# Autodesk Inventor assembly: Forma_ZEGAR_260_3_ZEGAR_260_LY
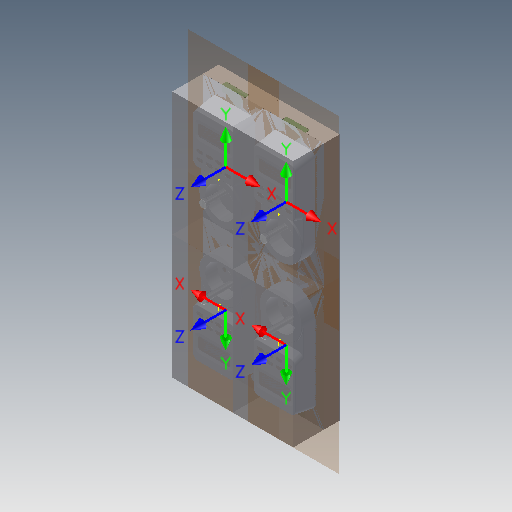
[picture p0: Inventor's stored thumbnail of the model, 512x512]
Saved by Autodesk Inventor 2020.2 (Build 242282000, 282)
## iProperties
Created: 2015-01
Part Number: Forma_ZEGAR_260_3_ZEGAR_260_LY
Document SubType Name: Assembly
Designer: F.Stasiak
Catalog Web Link: www.expertbooks.pl
Manager: www.cadconsulting.pl
Company: Fabian Stasiak CAD Consulting
Author: F.Stasiak
Subject: Zbiór ćwiczeń. Autodesk Inventor 2020. Kurs Professional
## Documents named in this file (10)
- C:\2020_Kurs_Professional\R6 Formy\Komponenty\Forma_ZEGAR_260_3_ZEGAR_260_LY.iam
- C:\2020_Kurs_Professional\R6 Formy\Komponenty\Forma_ZEGAR_260_3_ZEGAR_260_PZ.iam
- C:\2020_Kurs_Professional\R6 Formy\Komponenty\Forma_ZEGAR_260_3_ZEGAR_260_CV_2.ipt
- C:\2020_Kurs_Professional\R6 Formy\Komponenty\Forma_ZEGAR_260_3_ZEGAR_260_CV_3.ipt
- C:\2020_Kurs_Professional\R6 Formy\Komponenty\Forma_ZEGAR_260_3_ZEGAR_260_CV_4.ipt
- C:\2020_Kurs_Professional\R6 Formy\Komponenty\Forma_ZEGAR_260_3_ZEGAR_260_CV_1.ipt
- C:\2020_Kurs_Professional\R6 Formy\Komponenty\Forma_ZEGAR_260_3_ZEGAR_260_CR_2.ipt
- C:\2020_Kurs_Professional\R6 Formy\Komponenty\Forma_ZEGAR_260_3_ZEGAR_260_CR_3.ipt
- C:\2020_Kurs_Professional\R6 Formy\Komponenty\Forma_ZEGAR_260_3_ZEGAR_260_CR_4.ipt
- C:\2020_Kurs_Professional\R6 Formy\Komponenty\Forma_ZEGAR_260_3_ZEGAR_260_CR_1.ipt
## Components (12 placed, 9 different names)
1. Forma_ZEGAR_260_3_ZEGAR_260_PZ:1 [sub-assembly] — Równoległy:1, Równoległy:2, Równoległy:3, Równoległy:13, Równoległy:14, Równoległy:15, Równoległy:25, Równoległy:26, Równoległy:27
2. Forma_ZEGAR_260_3_ZEGAR_260_PZ:2 [sub-assembly] — Równoległy:4, Równoległy:5, Równoległy:6, Równoległy:16, Równoległy:17, Równoległy:18, Równoległy:28, Równoległy:29, Równoległy:30
3. Forma_ZEGAR_260_3_ZEGAR_260_PZ:3 [sub-assembly] — Równoległy:7, Równoległy:8, Równoległy:9, Równoległy:19, Równoległy:20, Równoległy:21, Równoległy:31, Równoległy:32, Równoległy:33
4. Forma_ZEGAR_260_3_ZEGAR_260_PZ:4 [sub-assembly] — Równoległy:10, Równoległy:11, Równoległy:12, Równoległy:22, Równoległy:23, Równoległy:24, Równoległy:34, Równoległy:35, Równoległy:36
5. Forma_ZEGAR_260_3_ZEGAR_260_CV_1:1 — Równoległy:13, Równoległy:14, Równoległy:15
6. Forma_ZEGAR_260_3_ZEGAR_260_CV_2:1 — Równoległy:16, Równoległy:17, Równoległy:18
7. Forma_ZEGAR_260_3_ZEGAR_260_CV_3:1 — Równoległy:19, Równoległy:20, Równoległy:21
8. Forma_ZEGAR_260_3_ZEGAR_260_CV_4:1 — Równoległy:22, Równoległy:23, Równoległy:24
9. Forma_ZEGAR_260_3_ZEGAR_260_CR_1:1 — Równoległy:25, Równoległy:26, Równoległy:27
10. Forma_ZEGAR_260_3_ZEGAR_260_CR_2:1 — Równoległy:28, Równoległy:29, Równoległy:30
11. Forma_ZEGAR_260_3_ZEGAR_260_CR_3:1 — Równoległy:31, Równoległy:32, Równoległy:33
12. Forma_ZEGAR_260_3_ZEGAR_260_CR_4:1 — Równoległy:34, Równoległy:35, Równoległy:36
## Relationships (36: Flush 36)
- Równoległy:1 [Flush]: Forma_ZEGAR_260_3_ZEGAR_260_PZ:1
- Równoległy:2 [Flush]: Forma_ZEGAR_260_3_ZEGAR_260_PZ:1
- Równoległy:3 [Flush]: Forma_ZEGAR_260_3_ZEGAR_260_PZ:1
- Równoległy:4 [Flush]: Forma_ZEGAR_260_3_ZEGAR_260_PZ:2
- Równoległy:5 [Flush]: Forma_ZEGAR_260_3_ZEGAR_260_PZ:2
- Równoległy:6 [Flush]: Forma_ZEGAR_260_3_ZEGAR_260_PZ:2
- Równoległy:7 [Flush]: Forma_ZEGAR_260_3_ZEGAR_260_PZ:3
- Równoległy:8 [Flush]: Forma_ZEGAR_260_3_ZEGAR_260_PZ:3
- Równoległy:9 [Flush]: Forma_ZEGAR_260_3_ZEGAR_260_PZ:3
- Równoległy:10 [Flush]: Forma_ZEGAR_260_3_ZEGAR_260_PZ:4
- Równoległy:11 [Flush]: Forma_ZEGAR_260_3_ZEGAR_260_PZ:4
- Równoległy:12 [Flush]: Forma_ZEGAR_260_3_ZEGAR_260_PZ:4
- Równoległy:13 [Flush]: Forma_ZEGAR_260_3_ZEGAR_260_PZ:1 ↔ Forma_ZEGAR_260_3_ZEGAR_260_CV_1:1
- Równoległy:14 [Flush]: Forma_ZEGAR_260_3_ZEGAR_260_PZ:1 ↔ Forma_ZEGAR_260_3_ZEGAR_260_CV_1:1
- Równoległy:15 [Flush]: Forma_ZEGAR_260_3_ZEGAR_260_PZ:1 ↔ Forma_ZEGAR_260_3_ZEGAR_260_CV_1:1
- Równoległy:16 [Flush]: Forma_ZEGAR_260_3_ZEGAR_260_PZ:2 ↔ Forma_ZEGAR_260_3_ZEGAR_260_CV_2:1
- Równoległy:17 [Flush]: Forma_ZEGAR_260_3_ZEGAR_260_PZ:2 ↔ Forma_ZEGAR_260_3_ZEGAR_260_CV_2:1
- Równoległy:18 [Flush]: Forma_ZEGAR_260_3_ZEGAR_260_PZ:2 ↔ Forma_ZEGAR_260_3_ZEGAR_260_CV_2:1
- Równoległy:19 [Flush]: Forma_ZEGAR_260_3_ZEGAR_260_PZ:3 ↔ Forma_ZEGAR_260_3_ZEGAR_260_CV_3:1
- Równoległy:20 [Flush]: Forma_ZEGAR_260_3_ZEGAR_260_PZ:3 ↔ Forma_ZEGAR_260_3_ZEGAR_260_CV_3:1
- Równoległy:21 [Flush]: Forma_ZEGAR_260_3_ZEGAR_260_PZ:3 ↔ Forma_ZEGAR_260_3_ZEGAR_260_CV_3:1
- Równoległy:22 [Flush]: Forma_ZEGAR_260_3_ZEGAR_260_PZ:4 ↔ Forma_ZEGAR_260_3_ZEGAR_260_CV_4:1
- Równoległy:23 [Flush]: Forma_ZEGAR_260_3_ZEGAR_260_PZ:4 ↔ Forma_ZEGAR_260_3_ZEGAR_260_CV_4:1
- Równoległy:24 [Flush]: Forma_ZEGAR_260_3_ZEGAR_260_PZ:4 ↔ Forma_ZEGAR_260_3_ZEGAR_260_CV_4:1
- Równoległy:25 [Flush]: Forma_ZEGAR_260_3_ZEGAR_260_PZ:1 ↔ Forma_ZEGAR_260_3_ZEGAR_260_CR_1:1
- Równoległy:26 [Flush]: Forma_ZEGAR_260_3_ZEGAR_260_PZ:1 ↔ Forma_ZEGAR_260_3_ZEGAR_260_CR_1:1
- Równoległy:27 [Flush]: Forma_ZEGAR_260_3_ZEGAR_260_PZ:1 ↔ Forma_ZEGAR_260_3_ZEGAR_260_CR_1:1
- Równoległy:28 [Flush]: Forma_ZEGAR_260_3_ZEGAR_260_PZ:2 ↔ Forma_ZEGAR_260_3_ZEGAR_260_CR_2:1
- Równoległy:29 [Flush]: Forma_ZEGAR_260_3_ZEGAR_260_PZ:2 ↔ Forma_ZEGAR_260_3_ZEGAR_260_CR_2:1
- Równoległy:30 [Flush]: Forma_ZEGAR_260_3_ZEGAR_260_PZ:2 ↔ Forma_ZEGAR_260_3_ZEGAR_260_CR_2:1
- Równoległy:31 [Flush]: Forma_ZEGAR_260_3_ZEGAR_260_PZ:3 ↔ Forma_ZEGAR_260_3_ZEGAR_260_CR_3:1
- Równoległy:32 [Flush]: Forma_ZEGAR_260_3_ZEGAR_260_PZ:3 ↔ Forma_ZEGAR_260_3_ZEGAR_260_CR_3:1
- Równoległy:33 [Flush]: Forma_ZEGAR_260_3_ZEGAR_260_PZ:3 ↔ Forma_ZEGAR_260_3_ZEGAR_260_CR_3:1
- Równoległy:34 [Flush]: Forma_ZEGAR_260_3_ZEGAR_260_PZ:4 ↔ Forma_ZEGAR_260_3_ZEGAR_260_CR_4:1
- Równoległy:35 [Flush]: Forma_ZEGAR_260_3_ZEGAR_260_PZ:4 ↔ Forma_ZEGAR_260_3_ZEGAR_260_CR_4:1
- Równoległy:36 [Flush]: Forma_ZEGAR_260_3_ZEGAR_260_PZ:4 ↔ Forma_ZEGAR_260_3_ZEGAR_260_CR_4:1
